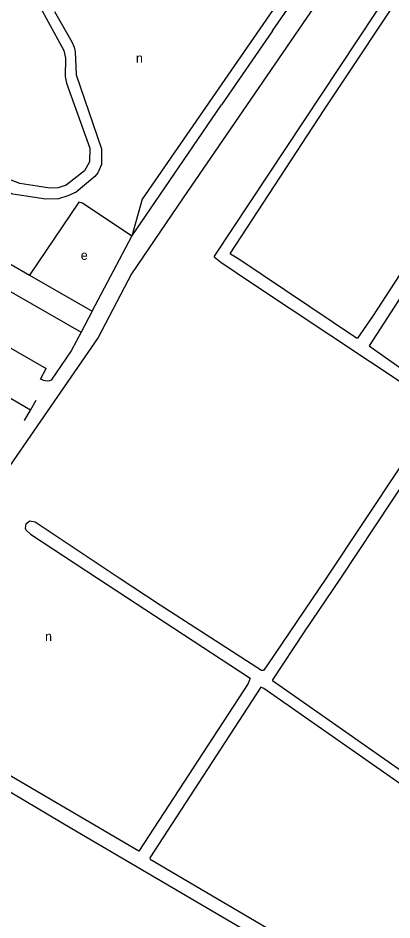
# Model space of a CAD drawing. Extents: x 157155 to 159285, y 385001 to 386651.
# Drawn here: x 158185 to 158344.8, y 385554.1 to 385939.1 of the extents above; entities that cross this region are included whole.
import ezdxf

# ---------------------------------------------------------------- set-up
doc = ezdxf.new("R2010")
doc.units = 0
doc.layers.add('BLT_Basislijn', color=7, linetype='Continuous')
doc.layers.add('BLT_Centroide', color=7, linetype='Continuous')

msp = doc.modelspace()

# ---------------------------------------------------------------- linework, layer by layer
at = {"layer": 'BLT_Basislijn'}
for p, q in [((158293.76, 385933.59), (158271.95, 385901.97)), ((158233.56, 385846.02), (158271.95, 385901.97)), ((158216.66, 385813.99), (158233.56, 385846.02)), ((158182.09, 385833.86), (158189.94, 385829.31)), ((158189.94, 385829.31), (158216.66, 385813.99)), ((158176.35, 385825.36), (158211.94, 385805.05)), ((158190.3, 385771.65), (158130.52, 385806.51)), ((158190.3, 385771.65), (158192.8, 385775.99)), ((158187.81, 385767.32), (158190.3, 385771.65))]:
    msp.add_line(p, q, dxfattribs=at)
for points in [[(158193.1, 385867.29), (158185.83, 385868.38), (158150.52, 385881.99), (158144.16, 385883.41), (158137.07, 385883.49), (158109.24, 385881.23), (158090.69, 385892.15), (158082.84, 385897.12), (158082.12, 385897.33), (158081.13, 385898.52), (158081.04, 385900.21), (158083.69, 385903.74), (158232.85, 386075.43)], [(158343.91, 385991.14), (158255.5, 385862.3), (158233.54, 385829.94)], [(158352.94, 385964.44), (158268.74, 385837.47), (158268.74, 385837.21), (158271.65, 385834.9), (158284.29, 385826.3), (158352.15, 385781.34)], [(158336.45, 385811.67), (158330.11, 385802.42), (158329.64, 385802.42), (158279.34, 385836.19), (158275.74, 385838.33), (158275.74, 385838.74), (158315.86, 385899.92), (158354.15, 385957.43), (158354.79, 385957.75), (158416.49, 385914.72), (158416.65, 385914.02), (158416.12, 385913.34), (158414.67, 385912.91), (158400.72, 385909.7), (158400.11, 385909.34), (158336.45, 385811.67)], [(158299.14, 385950.18), (158238.08, 385861.69), (158233.56, 385846.02)], [(158293.76, 385933.59), (158303.98, 385948.5)], [(158200.52, 385941.84), (158208.01, 385928.88), (158208.95, 385926.59), (158209.39, 385924.65), (158209.9, 385914.88), (158220.72, 385883.17), (158220.72, 385876.56), (158219.13, 385873.06), (158217.85, 385871.47), (158209.84, 385864.79), (158206.28, 385863.13), (158202.27, 385861.94), (158196.93, 385861.79), (158182.8, 385863.93), (158148.04, 385877.29), (158142.95, 385878.4), (158136.37, 385878.52), (158131.24, 385878.28), (158108.59, 385876.35)], [(158194.52, 385943.69), (158204.5, 385925.16), (158205.26, 385921.87), (158205.18, 385914.15), (158205.77, 385911.26), (158215.63, 385883.49), (158215.58, 385877.69), (158213.4, 385873.79), (158205.51, 385867.68), (158202.11, 385866.56), (158198.61, 385866.47), (158193.1, 385867.29)], [(158446.84, 385895.45), (158445.84, 385894.24), (158423.17, 385909.89), (158404.88, 385906), (158367.32, 385849.04), (158335.06, 385799.16), (158448.39, 385719.01), (158462.84, 385708.45), (158475.15, 385700), (158477.61, 385698.12)], [(158233.56, 385846.02), (158212.54, 385860.05), (158210.95, 385860.51), (158189.94, 385829.31)], [(158233.54, 385829.94), (158219.28, 385802.69), (158182.95, 385750), (158158.41, 385714.59), (158099.54, 385628.64)], [(158140.09, 385816.1), (158142.59, 385820.59), (158197.07, 385789.42)], [(158216.66, 385813.99), (158211.94, 385805.05)], [(158211.94, 385805.05), (158207.72, 385797.06), (158199.2, 385784.57), (158198.43, 385784.25), (158197.38, 385784.1), (158196.52, 385784.17), (158195.82, 385784.36), (158195.06, 385784.73), (158194.59, 385784.98), (158197.07, 385789.42)], [(158364.32, 385771.75), (158316.66, 385700), (158291.62, 385662.95), (158289.87, 385660.56), (158289.08, 385660.56), (158245.68, 385688.42), (158228.27, 385700), (158192.35, 385723.92), (158190.02, 385724.33), (158188.3, 385723.04), (158188.03, 385721.3), (158188.28, 385720.62), (158190.25, 385718.76), (158218.96, 385700), (158284.21, 385657.29), (158283.27, 385655.02), (158236.55, 385583.42), (158173.84, 385620.11)], [(158402.08, 385745.85), (158374.16, 385765.71), (158369.08, 385768.96), (158368.6, 385768.88), (158367.01, 385766.57), (158322.72, 385700), (158307.24, 385677.11), (158293.76, 385656.59), (158293.8, 385656.25), (158431.03, 385560.34)], [(158428.12, 385556.08), (158390.45, 385582.34), (158365.78, 385599.95), (158289.97, 385652.86), (158288.7, 385653.5), (158241.27, 385580.62), (158241.42, 385580.02), (158404.93, 385483.98)], [(158142.2, 385632.08), (158207.94, 385593.09), (158402.02, 385479.52)]]:
    msp.add_lwpolyline(points, dxfattribs=at)

# ---------------------------------------------------------------- texts
at = {"layer": 'BLT_Centroide'}
for s, p in [('n', (158235.38, 385919.96)), ('e', (158211.8, 385835.84)), ('n', (158196.54, 385673.16))]:
    msp.add_text(s, height=4, dxfattribs=at).set_placement(p)

doc.saveas('drawing.dxf')
